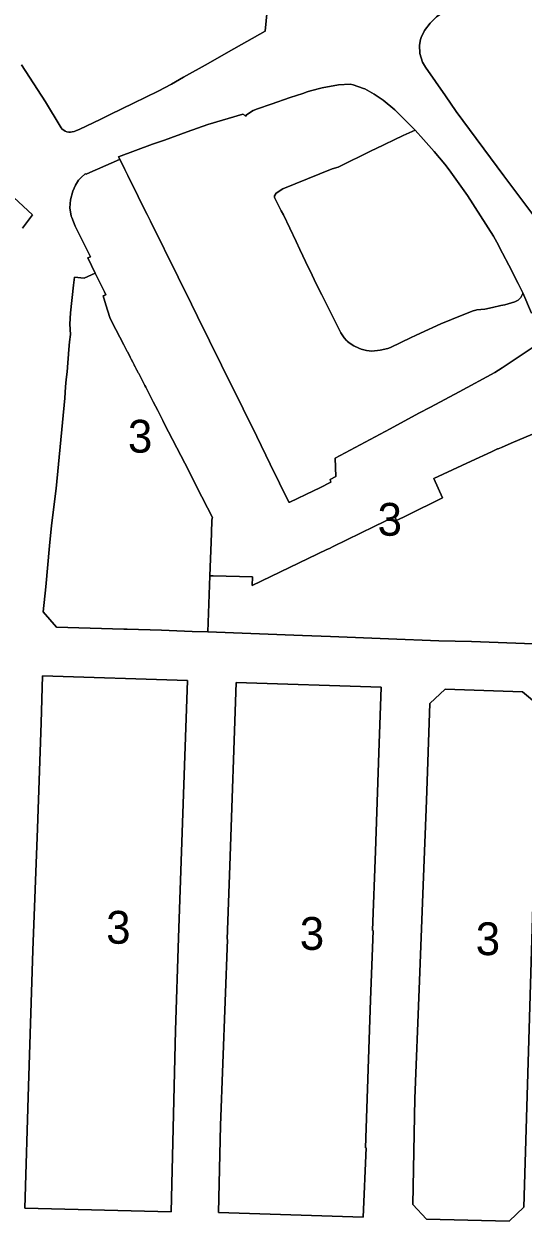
# Model space of a CAD drawing. Extents: x 598968 to 613553, y 4409678 to 4430833.
# Drawn here: x 607532.5 to 607715.2, y 4415644.8 to 4416082.8 of the extents above; entities that cross this region are included whole.
import ezdxf

# ---------------------------------------------------------------- set-up
doc = ezdxf.new("R2010")
doc.units = 0
for name, color, linetype in [('1', 7, 'Continuous'), ('ZONA 2. CARRERS DE CASES. Cases de trast', 7, 'Continuous'), ("ZONA 3. ILLES  D'EDIFICIS ENTRE MITGERES. EIXAMPLE.", 7, 'Continuous')]:
    doc.layers.add(name, color=color, linetype=linetype)

msp = doc.modelspace()

# ---------------------------------------------------------------- linework, layer by layer
at = {"layer": '1'}
for points in [[(607720.2778, 4416011.0364), (607708.2079, 4416027.136), (607690.728, 4416050.7253), (607686.8089, 4416056.3927), (607679.4981, 4416066.9649), (607678.4081, 4416068.7349), (607677.9141, 4416070.3355), (607677.4081, 4416071.9748), (607677.3081, 4416074.9848), (607677.7081, 4416077.0548), (607677.8581, 4416077.7848), (607679.138, 4416080.3848), (607681.248, 4416083.0448), (607683.548, 4416085.3148), (607685.9179, 4416087.0348), (607691.6579, 4416090.6549), (607698.8973, 4416095.1959), (607716.8354, 4416106.5031)], [(607716.8354, 4416106.5031), (607698.8973, 4416095.1959), (607691.6579, 4416090.6549), (607685.9179, 4416087.0348), (607683.548, 4416085.3148), (607681.248, 4416083.0448), (607679.138, 4416080.3848), (607677.8581, 4416077.7848), (607677.7081, 4416077.0548), (607677.3081, 4416074.9848), (607677.4081, 4416071.9748), (607677.9141, 4416070.3355), (607678.4081, 4416068.7349), (607679.4981, 4416066.9649), (607686.8089, 4416056.3927), (607690.728, 4416050.7253), (607708.2079, 4416027.136), (607720.2778, 4416011.0364)], [(607621.7387, 4416090.2436), (607620.8187, 4416080.0537), (607607.319, 4416072.5236), (607599.9491, 4416068.3335), (607590.9492, 4416063.2334), (607586.5161, 4416060.7071), (607581.6493, 4416058.2033), (607572.5994, 4416053.7332), (607564.0095, 4416049.5931), (607560.4096, 4416047.8231), (607552.8997, 4416044.203), (607551.429, 4416043.6921), (607550.8313, 4416043.4139), (607550.1972, 4416043.2333), (607549.5426, 4416043.1548), (607548.8839, 4416043.1802), (607548.2373, 4416043.3091), (607547.6191, 4416043.5382), (607547.0448, 4416043.8617), (607546.5284, 4416044.2715), (607546.0831, 4416044.7576), (607545.7198, 4416045.3078), (607540.3198, 4416054.2826), (607531.6056, 4416067.8205)], [(607719.0335, 4415856.0308), (607696.3786, 4415856.7877), (607684.4088, 4415857.1474), (607665.8941, 4415857.8427), (607644.7392, 4415858.6967), (607634.4448, 4415859.0868), (607599.7998, 4415860.3359), (607594.1005, 4415860.5407), (607582.83, 4415860.9456), (607570.3313, 4415861.3144), (607569.0147, 4415861.3619), (607544.4204, 4415862.1149), (607539.5605, 4415867.6547), (607540.4627, 4415876.8737), (607541.8803, 4415891.8146), (607542.6203, 4415899.2945), (607544.2602, 4415912.8144), (607547.4201, 4415945.8541), (607547.7201, 4415949.954), (607547.9793, 4415952.6951), (607548.2501, 4415955.494), (607548.93, 4415963.6539), (607549.2, 4415966.4439), (607549.47, 4415969.2038), (607549.3, 4415972.9838), (607549.59, 4415977.1237), (607550.6599, 4415987.2036), (607550.9523, 4415990.0711), (607554.5899, 4415989.7337), (607558.6198, 4415991.5237), (607555.8498, 4415997.1636), (607556.8098, 4415997.6036), (607551.2098, 4416008.8134), (607549.9727, 4416011.893), (607549.7798, 4416012.3733), (607549.3298, 4416015.4633), (607549.4998, 4416018.3633), (607550.3998, 4416021.5632), (607551.3798, 4416023.7932), (607552.4598, 4416025.5932), (607552.9097, 4416026.0932), (607553.5097, 4416026.7232), (607554.7713, 4416027.7561), (607554.9997, 4416027.9432), (607555.2097, 4416027.7435), (607557.7403, 4416028.8809), (607559.3802, 4416029.6126), (607567.4413, 4416033.1819), (607567.5791, 4416033.2432), (607567.1293, 4416034.1838), (607579.5889, 4416038.7161), (607583.899, 4416040.284), (607592.1789, 4416043.2741), (607599.7688, 4416046.0142), (607612.5986, 4416049.7544), (607613.4586, 4416049.2444), (607613.7833, 4416049.0557), (607614.0186, 4416049.4844), (607616.3386, 4416051.0744), (607617.9786, 4416051.6644), (607622.9385, 4416053.3845), (607629.9284, 4416055.8046), (607634.5283, 4416057.3447), (607636.1732, 4416057.8872), (607637.3783, 4416058.2847), (607641.6383, 4416059.4048), (607647.5899, 4416060.4771), (607651.8681, 4416060.7049), (607653.0181, 4416060.5149), (607656.7458, 4416059.137), (607657.2381, 4416058.955), (607660.748, 4416057.0451), (607664.0208, 4416054.8886), (607668.288, 4416051.3153), (607672.1679, 4416047.4154), (607675.6581, 4416043.8353), (607678.6982, 4416040.5153), (607682.6982, 4416036.0454), (607686.5881, 4416031.4755), (607688.1881, 4416029.4356), (607694.8048, 4416020.0236), (607704.398, 4416005.0962), (607705.568, 4416002.8862), (607707.688, 4415998.9163), (607710.028, 4415994.4964), (607713.418, 4415987.8065), (607714.748, 4415985.1166), (607715.1536, 4415984.3282), (607718.2276, 4415976.9471)], [(607718.2276, 4415976.9471), (607715.1536, 4415984.3282), (607715.0685, 4415984.1564), (607714.3679, 4415982.7268), (607713.4179, 4415981.7268), (607712.1379, 4415981.0368), (607708.4879, 4415980.0267), (607707.0554, 4415979.711), (607703.9695, 4415979.0309), (607701.228, 4415978.4266), (607699.7233, 4415978.2698), (607698.2181, 4415978.1166), (607697.8978, 4415978.0372), (607696.8781, 4415977.7865), (607692.9055, 4415976.1818), (607685.1427, 4415973.0457), (607685.1304, 4415973.0404), (607677.6183, 4415969.6663), (607675.7884, 4415968.7963), (607674.1784, 4415968.0063), (607666.7085, 4415964.3462), (607665.6685, 4415963.9962), (607662.8585, 4415963.4161), (607659.8486, 4415963.0661), (607657.8886, 4415963.306), (607655.9686, 4415963.796), (607655.0386, 4415964.136), (607653.2386, 4415964.9859), (607651.5787, 4415966.0559), (607650.7987, 4415966.6659), (607650.5762, 4415966.9106), (607649.6987, 4415967.8758), (607649.2226, 4415968.6638), (607648.5387, 4415969.7958), (607645.485, 4415975.8526), (607641.5488, 4415983.6453), (607640.3747, 4415986.0103), (607640.3712, 4415986.0172), (607638.7882, 4415989.2059), (607637.2064, 4415992.3922), (607636.6688, 4415993.4751), (607633.4922, 4416000.213), (607633.4887, 4416000.2203), (607632.1162, 4416003.1313), (607627.4988, 4416012.9249), (607626.6989, 4416014.4047), (607624.3988, 4416018.7148), (607624.2588, 4416019.3048), (607624.2488, 4416019.8648), (607624.7788, 4416020.8248), (607627.2087, 4416022.4148), (607645.3685, 4416029.805), (607647.4585, 4416030.3951), (607659.8968, 4416036.4241), (607661.1352, 4416037.0244), (607671.3082, 4416041.9553), (607675.6581, 4416043.8353), (607672.1679, 4416047.4154), (607668.288, 4416051.3153), (607664.0208, 4416054.8886), (607660.748, 4416057.0451), (607657.2381, 4416058.955), (607656.7458, 4416059.137), (607653.0181, 4416060.5149), (607651.8681, 4416060.7049), (607647.5899, 4416060.4771), (607641.6383, 4416059.4048), (607637.3783, 4416058.2847), (607636.1732, 4416057.8872), (607634.5283, 4416057.3447), (607629.9284, 4416055.8046), (607622.9385, 4416053.3845), (607617.9786, 4416051.6644), (607616.3386, 4416051.0744), (607614.0186, 4416049.4844), (607613.7833, 4416049.0557), (607613.4586, 4416049.2444), (607612.5986, 4416049.7544), (607599.7688, 4416046.0142), (607592.1789, 4416043.2741), (607583.899, 4416040.284), (607579.5889, 4416038.7161), (607567.1293, 4416034.1838), (607567.5791, 4416033.2432), (607569.3695, 4416029.4935), (607569.4795, 4416029.4835), (607570.5521, 4416027.3113), (607574.3295, 4416019.6621), (607576.0626, 4416016.1525), (607577.5686, 4416013.1028), (607578.7923, 4416010.6248), (607588.9183, 4415990.1193), (607593.807, 4415980.2199), (607596.0032, 4415975.7733), (607604.8327, 4415957.8997), (607607.6506, 4415952.1831), (607607.6807, 4415952.122), (607617.6972, 4415931.7905), (607622.6655, 4415921.6937), (607629.5092, 4415907.786), (607629.8692, 4415907.776), (607638.4391, 4415911.9761), (607640.7641, 4415913.0972), (607640.7681, 4415913.0991), (607644.889, 4415915.0862), (607644.549, 4415916.0661), (607646.709, 4415917.2062), (607646.409, 4415923.8561), (607666.552, 4415934.6729), (607677.0984, 4415940.3366), (607681.2617, 4415942.5728), (607691.7684, 4415948.2166), (607704.8482, 4415955.2468), (607707.5781, 4415956.9368), (607713.3981, 4415960.8268), (607718.8391, 4415964.4709)], [(607718.8391, 4415964.4709), (607713.3981, 4415960.8268), (607707.5781, 4415956.9368), (607704.8482, 4415955.2468), (607691.7684, 4415948.2166), (607681.2617, 4415942.5728), (607677.0984, 4415940.3366), (607666.552, 4415934.6729), (607646.409, 4415923.8561), (607646.709, 4415917.2062), (607644.549, 4415916.0661), (607644.889, 4415915.0862), (607640.7681, 4415913.0991), (607640.7641, 4415913.0972), (607638.4391, 4415911.9761), (607629.8692, 4415907.776), (607629.5092, 4415907.786), (607622.6655, 4415921.6937), (607617.6972, 4415931.7905), (607607.6807, 4415952.122), (607607.6506, 4415952.1831), (607604.8327, 4415957.8997), (607596.0032, 4415975.7733), (607593.807, 4415980.2199), (607588.9183, 4415990.1193), (607578.7923, 4416010.6248), (607577.5686, 4416013.1028), (607576.0626, 4416016.1525), (607574.3295, 4416019.6621), (607570.5521, 4416027.3113), (607569.4795, 4416029.4835), (607569.3695, 4416029.4935), (607567.5791, 4416033.2432), (607567.4413, 4416033.1819), (607559.3802, 4416029.6126), (607557.7403, 4416028.8809), (607555.2097, 4416027.7435), (607554.9997, 4416027.9432), (607554.7713, 4416027.7561), (607553.5097, 4416026.7232), (607552.9097, 4416026.0932), (607552.4598, 4416025.5932), (607551.3798, 4416023.7932), (607550.3998, 4416021.5632), (607549.4998, 4416018.3633), (607549.3298, 4416015.4633), (607549.7798, 4416012.3733), (607549.9727, 4416011.893), (607551.2098, 4416008.8134), (607556.8098, 4415997.6036), (607555.8498, 4415997.1636), (607558.6198, 4415991.5237), (607561.9428, 4415984.7754), (607562.5098, 4415983.6239), (607561.4498, 4415983.2439), (607562.4482, 4415980.0256), (607563.8943, 4415975.3646), (607564.6801, 4415973.8415), (607566.1284, 4415971.0344), (607569.0556, 4415965.3608), (607569.7001, 4415964.1117), (607570.3283, 4415962.8941), (607570.3804, 4415962.7932), (607570.8238, 4415961.9338), (607571.3571, 4415960.9001), (607571.7389, 4415960.1602), (607572.303, 4415959.0668), (607572.5508, 4415958.5866), (607572.8292, 4415958.047), (607573.1125, 4415957.4979), (607573.2129, 4415957.3033), (607573.3058, 4415957.1233), (607573.3507, 4415957.0363), (607573.4745, 4415956.7963), (607573.5561, 4415956.6381), (607573.5869, 4415956.5784), (607573.6255, 4415956.5036), (607573.6911, 4415956.3764), (607573.831, 4415956.1051), (607573.9014, 4415955.9686), (607574.0886, 4415955.6057), (607574.1882, 4415955.4126), (607574.3461, 4415955.1065), (607574.4922, 4415954.8233), (607575.6204, 4415952.6365), (607576.7227, 4415950.4999), (607577.0615, 4415949.8433), (607578.6499, 4415946.7646), (607579.8165, 4415944.5036), (607579.8222, 4415944.4924), (607581.4707, 4415941.2973), (607583.3397, 4415937.6748), (607583.9878, 4415936.3898), (607591.3392, 4415922.0578), (607597.6334, 4415909.7868), (607597.6486, 4415909.7573), (607599.6856, 4415905.786), (607601.5496, 4415902.1655), (607601.2896, 4415901.3755), (607601.1309, 4415896.3927), (607601.1291, 4415896.341), (607600.5598, 4415880.9202), (607601.7334, 4415880.8845), (607616.1195, 4415880.486), (607616.0795, 4415877.316), (607643.4218, 4415890.4806), (607644.3191, 4415890.9164), (607645.7325, 4415891.6062), (607660.7023, 4415898.9214), (607668.2188, 4415902.6167), (607668.8588, 4415901.0468), (607672.6487, 4415902.8768), (607685.6986, 4415909.367), (607682.5386, 4415916.5268), (607696.1415, 4415922.7607), (607703.6391, 4415926.2174), (607704.8971, 4415926.8019), (607705.8983, 4415927.2671), (607706.1382, 4415927.3695), (607707.3133, 4415927.8711), (607710.8387, 4415929.3761), (607723.2678, 4415934.6867)], [(607525.3301, 4416022.4028), (607535.61, 4416012.8831), (607531.9301, 4416008.0231)]]:
    msp.add_lwpolyline(points, dxfattribs=at)
for points in [[(607715.1536, 4415984.3282), (607714.748, 4415985.1166), (607713.418, 4415987.8065), (607710.028, 4415994.4964), (607707.688, 4415998.9163), (607705.568, 4416002.8862), (607704.398, 4416005.0962), (607694.8048, 4416020.0236), (607688.1881, 4416029.4356), (607686.5881, 4416031.4755), (607682.6982, 4416036.0454), (607678.6982, 4416040.5153), (607675.6581, 4416043.8353), (607671.3082, 4416041.9553), (607661.1352, 4416037.0244), (607659.8968, 4416036.4241), (607647.4585, 4416030.3951), (607645.3685, 4416029.805), (607627.2087, 4416022.4148), (607624.7788, 4416020.8248), (607624.2488, 4416019.8648), (607624.2588, 4416019.3048), (607624.3988, 4416018.7148), (607626.6989, 4416014.4047), (607627.4988, 4416012.9249), (607632.1162, 4416003.1313), (607633.4887, 4416000.2203), (607633.4922, 4416000.213), (607636.6688, 4415993.4751), (607637.2064, 4415992.3922), (607638.7882, 4415989.2059), (607640.3712, 4415986.0172), (607640.3747, 4415986.0103), (607641.5488, 4415983.6453), (607645.485, 4415975.8526), (607648.5387, 4415969.7958), (607649.2226, 4415968.6638), (607649.6987, 4415967.8758), (607650.5762, 4415966.9106), (607650.7987, 4415966.6659), (607651.5787, 4415966.0559), (607653.2386, 4415964.9859), (607655.0386, 4415964.136), (607655.9686, 4415963.796), (607657.8886, 4415963.306), (607659.8486, 4415963.0661), (607662.8585, 4415963.4161), (607665.6685, 4415963.9962), (607666.7085, 4415964.3462), (607674.1784, 4415968.0063), (607675.7884, 4415968.7963), (607677.6183, 4415969.6663), (607685.1304, 4415973.0404), (607685.1427, 4415973.0457), (607692.9055, 4415976.1818), (607696.8781, 4415977.7865), (607697.8978, 4415978.0372), (607698.2181, 4415978.1166), (607699.7233, 4415978.2698), (607701.228, 4415978.4266), (607703.9695, 4415979.0309), (607707.0554, 4415979.711), (607708.4879, 4415980.0267), (607712.1379, 4415981.0368), (607713.4179, 4415981.7268), (607714.3679, 4415982.7268), (607715.0685, 4415984.1564)], [(607591.2701, 4415811.5063), (607589.1003, 4415748.447), (607587.9804, 4415714.5374), (607586.7906, 4415663.398), (607586.3407, 4415648.2582), (607532.8013, 4415649.5672), (607534.1811, 4415694.1267), (607535.7309, 4415743.7761), (607537.4108, 4415788.3956), (607538.8106, 4415827.1252), (607539.3405, 4415844.325), (607592.3699, 4415842.596)], [(607662.4291, 4415816.1775), (607661.1393, 4415780.1579), (607660.0694, 4415751.1883), (607660.2694, 4415751.1783), (607659.3495, 4415725.6486), (607657.5597, 4415671.6392), (607657.8137, 4415671.6277), (607656.6598, 4415646.2395), (607603.6905, 4415647.9785), (607604.4904, 4415679.8481), (607607.0301, 4415747.8923), (607606.8901, 4415747.8973), (607607.87, 4415774.767), (607610.1997, 4415841.8563), (607663.2491, 4415840.1873)], [(607714.9485, 4415838.4282), (607720.9184, 4415833.4684), (607715.4891, 4415649.9805), (607710.1092, 4415644.8405), (607679.8495, 4415645.5899), (607674.8196, 4415650.8997), (607675.5894, 4415689.7193), (607677.1093, 4415729.6889), (607678.8091, 4415770.7584), (607679.859, 4415798.6881), (607681.1189, 4415834.1777), (607686.7188, 4415839.3877)]]:
    msp.add_lwpolyline(points, close=True, dxfattribs=at)
at = {"layer": 'ZONA 2. CARRERS DE CASES. Cases de trast'}
msp.add_lwpolyline([(607531.9301, 4416008.0231), (607535.61, 4416012.8831), (607525.3301, 4416022.4028)], dxfattribs=at)
at = {"layer": "ZONA 3. ILLES  D'EDIFICIS ENTRE MITGERES. EIXAMPLE."}
for points in [[(607531.6056, 4416067.8205), (607540.3198, 4416054.2826), (607545.7198, 4416045.3078), (607546.0831, 4416044.7576), (607546.5284, 4416044.2715), (607547.0448, 4416043.8617), (607547.6191, 4416043.5382), (607548.2373, 4416043.3091), (607548.8839, 4416043.1802), (607549.5426, 4416043.1548), (607550.1972, 4416043.2333), (607550.8313, 4416043.4139), (607551.429, 4416043.6921), (607552.8997, 4416044.203), (607560.4096, 4416047.8231), (607564.0095, 4416049.5931), (607572.5994, 4416053.7332), (607581.6493, 4416058.2033), (607586.5161, 4416060.7071), (607590.9492, 4416063.2334), (607599.9491, 4416068.3335), (607607.319, 4416072.5236), (607620.8187, 4416080.0537), (607621.7387, 4416090.2436)], [(607723.2678, 4415934.6867), (607710.8387, 4415929.3761), (607707.3133, 4415927.8711), (607706.1382, 4415927.3695), (607705.8983, 4415927.2671), (607704.8971, 4415926.8019), (607703.6391, 4415926.2174), (607696.1415, 4415922.7607), (607682.5386, 4415916.5268), (607685.6986, 4415909.367), (607672.6487, 4415902.8768), (607668.8588, 4415901.0468), (607668.2188, 4415902.6167), (607660.7023, 4415898.9214), (607645.7325, 4415891.6062), (607644.3191, 4415890.9164), (607643.4218, 4415890.4806), (607616.0795, 4415877.316), (607616.1195, 4415880.486), (607601.7334, 4415880.8845), (607600.5598, 4415880.9202), (607599.7998, 4415860.3359), (607634.4448, 4415859.0868), (607644.7392, 4415858.6967), (607665.8941, 4415857.8427), (607684.4088, 4415857.1474), (607696.3786, 4415856.7877), (607719.0335, 4415856.0308)]]:
    msp.add_lwpolyline(points, dxfattribs=at)
for points in [[(607600.5598, 4415880.9202), (607601.1291, 4415896.341), (607601.1309, 4415896.3927), (607601.2896, 4415901.3755), (607601.5496, 4415902.1655), (607599.6856, 4415905.786), (607597.6486, 4415909.7573), (607597.6334, 4415909.7868), (607591.3392, 4415922.0578), (607583.9878, 4415936.3898), (607583.3397, 4415937.6748), (607581.4707, 4415941.2973), (607579.8222, 4415944.4924), (607579.8165, 4415944.5036), (607578.6499, 4415946.7646), (607577.0615, 4415949.8433), (607576.7227, 4415950.4999), (607575.6204, 4415952.6365), (607574.4922, 4415954.8233), (607574.3461, 4415955.1065), (607574.1882, 4415955.4126), (607574.0886, 4415955.6057), (607573.9014, 4415955.9686), (607573.831, 4415956.1051), (607573.6911, 4415956.3764), (607573.6255, 4415956.5036), (607573.5869, 4415956.5784), (607573.5561, 4415956.6381), (607573.4745, 4415956.7963), (607573.3507, 4415957.0363), (607573.3058, 4415957.1233), (607573.2129, 4415957.3033), (607573.1125, 4415957.4979), (607572.8292, 4415958.047), (607572.5508, 4415958.5866), (607572.303, 4415959.0668), (607571.7389, 4415960.1602), (607571.3571, 4415960.9001), (607570.8238, 4415961.9338), (607570.3804, 4415962.7932), (607570.3283, 4415962.8941), (607569.7001, 4415964.1117), (607569.0556, 4415965.3608), (607566.1284, 4415971.0344), (607564.6801, 4415973.8415), (607563.8943, 4415975.3646), (607562.4482, 4415980.0256), (607561.4498, 4415983.2439), (607562.5098, 4415983.6239), (607561.9428, 4415984.7754), (607558.6198, 4415991.5237), (607554.5899, 4415989.7337), (607550.9523, 4415990.0711), (607550.6599, 4415987.2036), (607549.59, 4415977.1237), (607549.3, 4415972.9838), (607549.47, 4415969.2038), (607549.2, 4415966.4439), (607548.93, 4415963.6539), (607548.2501, 4415955.494), (607547.9793, 4415952.6951), (607547.7201, 4415949.954), (607547.4201, 4415945.8541), (607544.2602, 4415912.8144), (607542.6203, 4415899.2945), (607541.8803, 4415891.8146), (607540.4627, 4415876.8737), (607539.5605, 4415867.6547), (607544.4204, 4415862.1149), (607569.0147, 4415861.3619), (607570.3313, 4415861.3144), (607582.83, 4415860.9456), (607594.1005, 4415860.5407), (607599.7998, 4415860.3359)], [(607586.7906, 4415663.398), (607587.9804, 4415714.5374), (607589.1003, 4415748.447), (607591.2701, 4415811.5063), (607592.3699, 4415842.596), (607539.3405, 4415844.325), (607538.8106, 4415827.1252), (607537.4108, 4415788.3956), (607535.7309, 4415743.7761), (607534.1811, 4415694.1267), (607532.8013, 4415649.5672), (607586.3407, 4415648.2582)], [(607657.8137, 4415671.6277), (607657.5597, 4415671.6392), (607659.3495, 4415725.6486), (607660.2694, 4415751.1783), (607660.0694, 4415751.1883), (607661.1393, 4415780.1579), (607662.4291, 4415816.1775), (607663.2491, 4415840.1873), (607610.1997, 4415841.8563), (607607.87, 4415774.767), (607606.8901, 4415747.8973), (607607.0301, 4415747.8923), (607604.4904, 4415679.8481), (607603.6905, 4415647.9785), (607656.6598, 4415646.2395)], [(607715.4891, 4415649.9805), (607720.9184, 4415833.4684), (607714.9485, 4415838.4282), (607686.7188, 4415839.3877), (607681.1189, 4415834.1777), (607679.859, 4415798.6881), (607678.8091, 4415770.7584), (607677.1093, 4415729.6889), (607675.5894, 4415689.7193), (607674.8196, 4415650.8997), (607679.8495, 4415645.5899), (607710.1092, 4415644.8405)]]:
    msp.add_lwpolyline(points, close=True, dxfattribs=at)

# ---------------------------------------------------------------- texts
for p in [(607570.555, 4415925.9298), (607661.9439, 4415895.534), (607562.5856, 4415746.2916), (607633.4698, 4415744.0479), (607697.869, 4415742.1141)]:
    msp.add_text('3', height=12, dxfattribs=at).set_placement(p)

doc.saveas('drawing.dxf')
